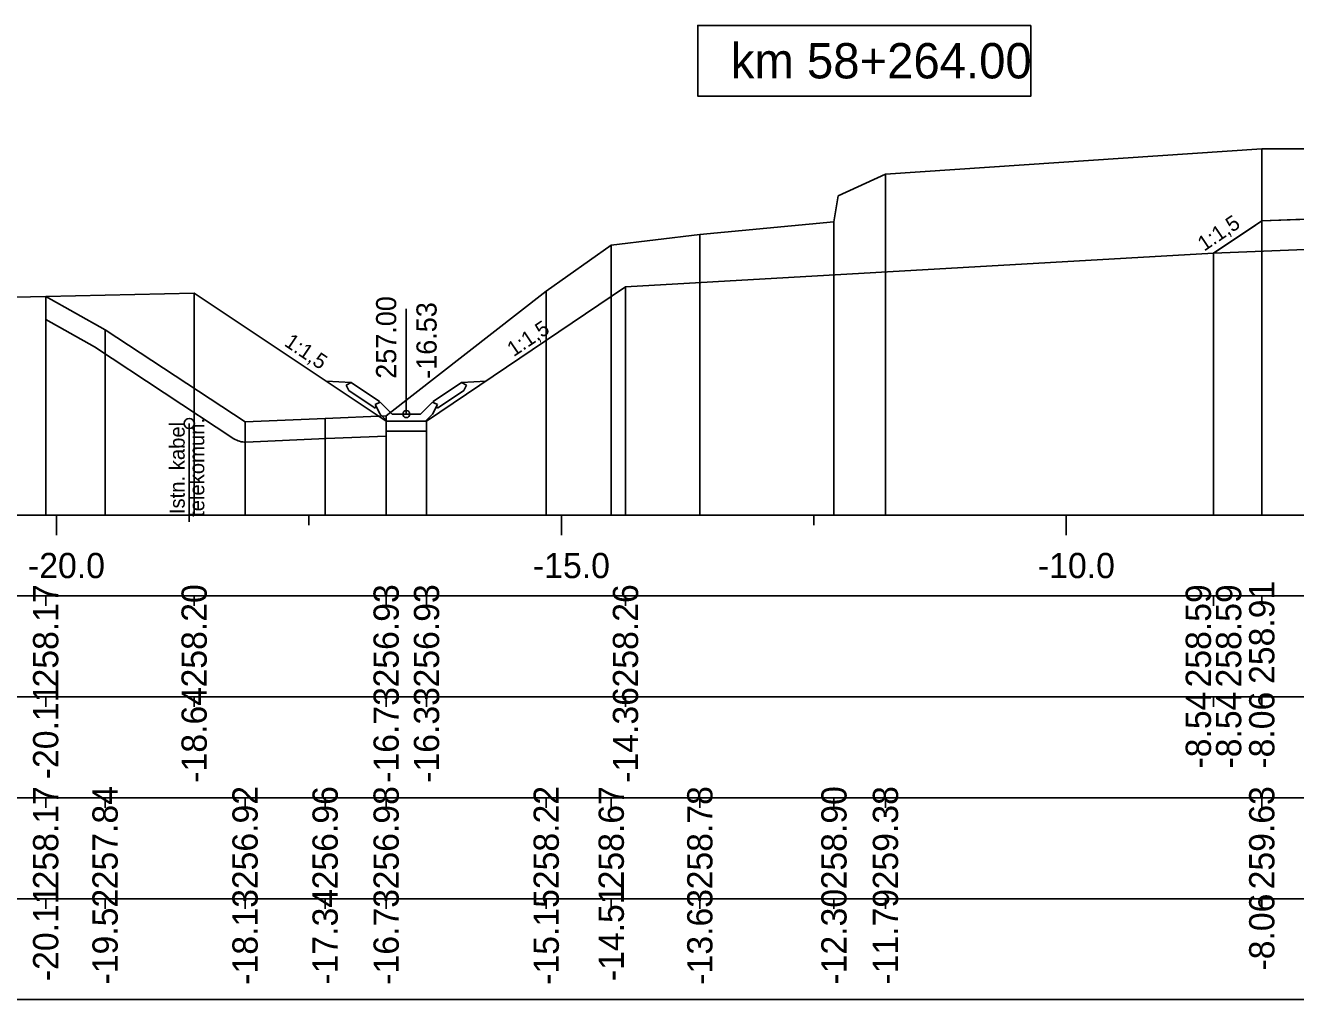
# Model space of a CAD drawing. Extents: x 6516023 to 6560129, y 5513077 to 5529206.
# Drawn here: x 6516537.16 to 6516549.73, y 5514501.31 to 5514510.96 of the extents above; entities that cross this region are included whole.
import ezdxf

# ---------------------------------------------------------------- set-up
doc = ezdxf.new("R2010")
doc.units = 0
for name, color, linetype in [('IR_default', 7, 'Continuous'), ('TOR_PRZEK_P-kable', 7, 'Continuous'), ('TOR_PRZEK_P-odwodnienie', 7, 'Continuous'), ('TOR_PRZEK_P-opisy', 7, 'Continuous'), ('TOR_PRZEK_P-schodkowanie+wymiana', 7, 'Continuous'), ('TOR_PRZEK_P-tabelka istniejace', 7, 'Continuous'), ('TOR_PRZEK_P-tabelka projektowane', 7, 'Continuous'), ('TOR_PRZEK_P-teren istniejacy', 7, 'Continuous'), ('TOR_PRZEK_P-uklad odniesienia', 7, 'Continuous'), ('TOR_PRZEK_P-warstwa ochronna I', 7, 'Continuous'), ('TOR_PRZEK_P-warstwa ochronna II', 7, 'Continuous')]:
    doc.layers.add(name, color=color, linetype=linetype)

msp = doc.modelspace()

# ---------------------------------------------------------------- linework, layer by layer
at = {"layer": 'IR_default'}
msp.add_lwpolyline([(6516537.357, 5514508.272), (6516538.827, 5514508.304), (6516540.728, 5514507.036), (6516541.128, 5514507.036), (6516543.098, 5514508.367), (6516548.92, 5514508.699), (6516549.272, 5514508.934), (6516549.398, 5514509.019), (6516549.868, 5514509.037)], dxfattribs=at)
at = {"layer": 'TOR_PRZEK_P-kable'}
msp.add_line((6516538.779, 5514507.013), (6516538.779, 5514506.039), dxfattribs=at)
msp.add_circle((6516538.779, 5514507.013), 0.05, dxfattribs=at)
at = {"layer": 'TOR_PRZEK_P-odwodnienie'}
for p, q in [((6516540.928, 5514507.106), (6516540.928, 5514508.15)), ((6516540.664, 5514507.232), (6516540.383, 5514507.419)), ((6516541.193, 5514507.232), (6516541.473, 5514507.419)), ((6516540.619, 5514507.165), (6516540.358, 5514507.34)), ((6516541.237, 5514507.165), (6516541.499, 5514507.34)), ((6516540.63, 5514507.182), (6516540.619, 5514507.165)), ((6516540.621, 5514507.201), (6516540.668, 5514507.225)), ((6516540.664, 5514507.232), (6516540.655, 5514507.219)), ((6516540.788, 5514507.106), (6516540.668, 5514507.225)), ((6516541.068, 5514507.106), (6516541.188, 5514507.225)), ((6516541.188, 5514507.225), (6516541.236, 5514507.201)), ((6516541.193, 5514507.232), (6516541.201, 5514507.219)), ((6516541.226, 5514507.182), (6516541.237, 5514507.165)), ((6516540.738, 5514507.036), (6516541.118, 5514507.036)), ((6516540.788, 5514507.106), (6516541.068, 5514507.106))]:
    msp.add_line(p, q, dxfattribs=at)
for points in [[(6516540.137, 5514507.431), (6516540.383, 5514507.419)], [(6516540.333, 5514507.392), (6516540.383, 5514507.419)], [(6516540.333, 5514507.392), (6516540.358, 5514507.34)], [(6516541.72, 5514507.431), (6516541.473, 5514507.419)], [(6516541.524, 5514507.392), (6516541.473, 5514507.419)], [(6516541.524, 5514507.392), (6516541.499, 5514507.34)], [(6516540.655, 5514507.219), (6516540.62, 5514507.201)], [(6516540.62, 5514507.201), (6516540.63, 5514507.182)], [(6516540.668, 5514507.106), (6516540.621, 5514507.201)], [(6516541.188, 5514507.106), (6516541.236, 5514507.201)], [(6516541.201, 5514507.219), (6516541.237, 5514507.201)], [(6516541.237, 5514507.201), (6516541.226, 5514507.182)], [(6516540.738, 5514507.036), (6516540.668, 5514507.106)], [(6516541.128, 5514507.036), (6516540.728, 5514507.036), (6516540.728, 5514506.936), (6516541.128, 5514506.936), (6516541.128, 5514507.036)], [(6516541.118, 5514507.036), (6516541.188, 5514507.106)]]:
    msp.add_lwpolyline(points, dxfattribs=at)
msp.add_circle((6516540.928, 5514507.106), 0.035, dxfattribs=at)
at = {"layer": 'TOR_PRZEK_P-schodkowanie+wymiana'}
for points in [[(6516537.357, 5514508.042), (6516537.841, 5514507.771), (6516539.221, 5514506.862)], [(6516539.34, 5514506.829), (6516540.133, 5514506.863), (6516540.728, 5514506.888)]]:
    msp.add_lwpolyline(points, dxfattribs=at)
msp.add_arc((6516539.331, 5514507.029), 0.2, 236.6356, 272.4752, dxfattribs=at)
at = {"layer": 'TOR_PRZEK_P-tabelka istniejace'}
for p, q in [((6516537.357, 5514503.206), (6516537.357, 5514503.306)), ((6516537.945, 5514503.206), (6516537.945, 5514503.306)), ((6516539.331, 5514503.206), (6516539.331, 5514503.306)), ((6516540.124, 5514503.206), (6516540.124, 5514503.306)), ((6516540.728, 5514503.206), (6516540.728, 5514503.306)), ((6516542.313, 5514503.206), (6516542.313, 5514503.306)), ((6516542.957, 5514503.206), (6516542.957, 5514503.306)), ((6516543.834, 5514503.206), (6516543.834, 5514503.306)), ((6516545.162, 5514503.206), (6516545.162, 5514503.306)), ((6516545.672, 5514503.206), (6516545.672, 5514503.306)), ((6516549.398, 5514503.206), (6516549.398, 5514503.306)), ((6516518.663, 5514502.306), (6516592.463, 5514502.306)), ((6516537.357, 5514502.206), (6516537.357, 5514502.306)), ((6516537.945, 5514502.206), (6516537.945, 5514502.306)), ((6516539.331, 5514502.206), (6516539.331, 5514502.306)), ((6516540.124, 5514502.206), (6516540.124, 5514502.306)), ((6516540.728, 5514502.206), (6516540.728, 5514502.306)), ((6516542.313, 5514502.206), (6516542.313, 5514502.306)), ((6516542.957, 5514502.206), (6516542.957, 5514502.306)), ((6516543.834, 5514502.206), (6516543.834, 5514502.306)), ((6516545.162, 5514502.206), (6516545.162, 5514502.306)), ((6516545.672, 5514502.206), (6516545.672, 5514502.306)), ((6516549.398, 5514502.206), (6516549.398, 5514502.306))]:
    msp.add_line(p, q, dxfattribs=at)
for points in [[(6516549.398, 5514509.735), (6516549.398, 5514506.306), (6516549.398, 5514506.176), (6516549.398, 5514506.106)], [(6516545.672, 5514509.483), (6516545.672, 5514506.306), (6516545.672, 5514506.176), (6516545.672, 5514506.106)], [(6516545.162, 5514509.01), (6516545.162, 5514506.306), (6516545.162, 5514506.176), (6516545.162, 5514506.106)], [(6516542.957, 5514508.779), (6516542.957, 5514506.306), (6516542.957, 5514506.176), (6516542.957, 5514506.106)], [(6516543.834, 5514508.884), (6516543.834, 5514506.306), (6516543.834, 5514506.176), (6516543.834, 5514506.106)], [(6516537.357, 5514508.272), (6516537.357, 5514506.306), (6516537.357, 5514506.176), (6516537.357, 5514506.106)], [(6516542.313, 5514508.323), (6516542.313, 5514506.306), (6516542.313, 5514506.176), (6516542.313, 5514506.106)], [(6516537.945, 5514507.942), (6516537.945, 5514506.306), (6516537.945, 5514506.176), (6516537.945, 5514506.106)], [(6516539.331, 5514507.029), (6516539.331, 5514506.306), (6516539.331, 5514506.176), (6516539.331, 5514506.106)], [(6516540.124, 5514507.063), (6516540.124, 5514506.306), (6516540.124, 5514506.176), (6516540.124, 5514506.106)], [(6516540.728, 5514507.088), (6516540.728, 5514506.306), (6516540.728, 5514506.176), (6516540.728, 5514506.106)]]:
    msp.add_lwpolyline(points, dxfattribs=at)
msp.add_lwpolyline([(6516518.663, 5514503.306), (6516518.663, 5514501.306), (6516592.463, 5514501.306), (6516592.463, 5514503.306)], close=True, dxfattribs=at)
at = {"layer": 'TOR_PRZEK_P-tabelka projektowane'}
for p, q in [((6516537.357, 5514505.206), (6516537.357, 5514505.306)), ((6516538.827, 5514505.206), (6516538.827, 5514505.306)), ((6516540.728, 5514505.206), (6516540.728, 5514505.306)), ((6516541.128, 5514505.206), (6516541.128, 5514505.306)), ((6516543.098, 5514505.206), (6516543.098, 5514505.306)), ((6516548.92, 5514505.206), (6516548.92, 5514505.306)), ((6516549.398, 5514505.206), (6516549.398, 5514505.306)), ((6516518.663, 5514504.306), (6516592.463, 5514504.306)), ((6516537.357, 5514504.206), (6516537.357, 5514504.306)), ((6516538.827, 5514504.206), (6516538.827, 5514504.306)), ((6516540.728, 5514504.206), (6516540.728, 5514504.306)), ((6516541.128, 5514504.206), (6516541.128, 5514504.306)), ((6516543.098, 5514504.206), (6516543.098, 5514504.306)), ((6516548.92, 5514504.206), (6516548.92, 5514504.306)), ((6516549.398, 5514504.206), (6516549.398, 5514504.306))]:
    msp.add_line(p, q, dxfattribs=at)
for points in [[(6516549.398, 5514509.019), (6516549.398, 5514506.306), (6516549.398, 5514506.176), (6516549.398, 5514506.106)], [(6516548.92, 5514508.699), (6516548.92, 5514506.306), (6516548.92, 5514506.176), (6516548.92, 5514506.106)], [(6516537.357, 5514508.272), (6516537.357, 5514506.306), (6516537.357, 5514506.176), (6516537.357, 5514506.106)], [(6516538.827, 5514508.304), (6516538.827, 5514506.306), (6516538.827, 5514506.176), (6516538.827, 5514506.106)], [(6516543.098, 5514508.367), (6516543.098, 5514506.306), (6516543.098, 5514506.176), (6516543.098, 5514506.106)], [(6516540.728, 5514507.036), (6516540.728, 5514506.306), (6516540.728, 5514506.176), (6516540.728, 5514506.106)], [(6516541.128, 5514507.036), (6516541.128, 5514506.306), (6516541.128, 5514506.176), (6516541.128, 5514506.106)]]:
    msp.add_lwpolyline(points, dxfattribs=at)
msp.add_lwpolyline([(6516518.663, 5514505.306), (6516518.663, 5514503.306), (6516592.463, 5514503.306), (6516592.463, 5514505.306)], close=True, dxfattribs=at)
at = {"layer": 'TOR_PRZEK_P-teren istniejacy'}
msp.add_lwpolyline([(6516531.876, 5514508.152), (6516537.357, 5514508.272), (6516537.945, 5514507.942), (6516539.331, 5514507.029), (6516540.124, 5514507.063), (6516540.728, 5514507.088), (6516542.313, 5514508.323), (6516542.957, 5514508.779), (6516543.834, 5514508.884), (6516545.162, 5514509.01), (6516545.205, 5514509.267), (6516545.672, 5514509.483), (6516549.398, 5514509.735), (6516550.209, 5514509.732)], dxfattribs=at)
at = {"layer": 'TOR_PRZEK_P-uklad odniesienia'}
for p, q in [((6516522.463, 5514506.106), (6516592.463, 5514506.106)), ((6516537.463, 5514505.906), (6516537.463, 5514506.106)), ((6516539.963, 5514506.006), (6516539.963, 5514506.106)), ((6516542.463, 5514505.906), (6516542.463, 5514506.106)), ((6516544.963, 5514506.006), (6516544.963, 5514506.106)), ((6516547.463, 5514505.906), (6516547.463, 5514506.106))]:
    msp.add_line(p, q, dxfattribs=at)
msp.add_lwpolyline([(6516547.113, 5514510.956), (6516543.813, 5514510.956), (6516543.813, 5514510.256), (6516547.113, 5514510.256)], close=True, dxfattribs=at)
at = {"layer": 'TOR_PRZEK_P-warstwa ochronna I'}
msp.add_lwpolyline([(6516548.92, 5514508.699), (6516559.488, 5514509.122), (6516569.742, 5514508.712)], dxfattribs=at)
at = {"layer": 'TOR_PRZEK_P-warstwa ochronna II'}
msp.add_lwpolyline([(6516537.357, 5514508.272), (6516538.827, 5514508.304), (6516540.728, 5514507.036), (6516541.128, 5514507.036), (6516543.098, 5514508.367), (6516548.92, 5514508.699), (6516549.398, 5514509.019), (6516549.985, 5514509.042), (6516558.213, 5514509.371), (6516559.488, 5514509.422), (6516560.763, 5514509.372), (6516568.657, 5514509.055), (6516569.263, 5514509.031), (6516569.742, 5514508.712), (6516571.563, 5514508.539), (6516573.203, 5514507.446), (6516573.603, 5514507.446), (6516574.404, 5514507.98)], dxfattribs=at)

# ---------------------------------------------------------------- texts
at = {"layer": 'TOR_PRZEK_P-kable'}
for s, height, p in [('Istn. kabel', 0.14999, (6516538.734, 5514506.115)), ('telekomun.', 0.15, (6516538.928, 5514506.087))]:
    msp.add_text(s, height=height, rotation=90.0511, dxfattribs=at).set_placement(p)
at = {"layer": 'TOR_PRZEK_P-odwodnienie'}
for s, p in [('257.00', (6516540.828, 5514507.456)), ('-16.53', (6516541.228, 5514507.456))]:
    msp.add_text(s, height=0.2, rotation=90, dxfattribs=at).set_placement(p)
at = {"layer": 'TOR_PRZEK_P-opisy'}
for rotation, p in [(34.0701, (6516548.828, 5514508.714)), (34.0701, (6516541.991, 5514507.669)), (325.9299, (6516539.71, 5514507.79))]:
    msp.add_text('1:1,5', height=0.15, rotation=rotation, dxfattribs=at).set_placement(p)
at = {"layer": 'TOR_PRZEK_P-tabelka istniejace'}
for s, p in [('258.17', (6516537.482, 5514502.398)), ('257.84', (6516538.07, 5514502.399)), ('256.92', (6516539.456, 5514502.4)), ('256.96', (6516540.249, 5514502.398)), ('256.98', (6516540.853, 5514502.398)), ('258.22', (6516542.438, 5514502.4)), ('258.67', (6516543.082, 5514502.398)), ('258.78', (6516543.959, 5514502.398)), ('258.90', (6516545.287, 5514502.398)), ('259.38', (6516545.797, 5514502.398)), ('259.63', (6516549.523, 5514502.398)), ('-20.11', (6516537.482, 5514501.489)), ('-19.52', (6516538.07, 5514501.456)), ('-18.13', (6516539.456, 5514501.454)), ('-17.34', (6516540.249, 5514501.455)), ('-16.73', (6516540.853, 5514501.454)), ('-15.15', (6516542.438, 5514501.453)), ('-14.51', (6516543.082, 5514501.489)), ('-13.63', (6516543.959, 5514501.454)), ('-12.30', (6516545.287, 5514501.455)), ('-11.79', (6516545.797, 5514501.455)), ('-8.06', (6516549.523, 5514501.594))]:
    msp.add_text(s, height=0.25, rotation=90, dxfattribs=at).set_placement(p)
at = {"layer": 'TOR_PRZEK_P-tabelka projektowane'}
for s, p in [('258.17', (6516537.482, 5514504.398)), ('258.20', (6516538.952, 5514504.398)), ('256.93', (6516540.853, 5514504.398)), ('256.93', (6516541.253, 5514504.398)), ('258.26', (6516543.223, 5514504.398)), ('258.59', (6516548.895, 5514504.398)), ('258.59', (6516549.195, 5514504.398)), ('258.91', (6516549.523, 5514504.433)), ('-20.11', (6516537.482, 5514503.489)), ('-18.64', (6516538.952, 5514503.455)), ('-16.73', (6516540.853, 5514503.454)), ('-16.33', (6516541.253, 5514503.454)), ('-14.36', (6516543.223, 5514503.454)), ('-8.54', (6516548.895, 5514503.595)), ('-8.54', (6516549.195, 5514503.595)), ('-8.06', (6516549.523, 5514503.594))]:
    msp.add_text(s, height=0.25, rotation=90, dxfattribs=at).set_placement(p)
at = {"layer": 'TOR_PRZEK_P-uklad odniesienia'}
for s, height, p in [('km 58+264.00', 0.35, (6516544.141, 5514510.431)), ('-20.0', 0.25, (6516537.182, 5514505.481)), ('-15.0', 0.25, (6516542.182, 5514505.481)), ('-10.0', 0.25, (6516547.182, 5514505.481))]:
    msp.add_text(s, height=height, dxfattribs=at).set_placement(p)

doc.saveas('drawing.dxf')
